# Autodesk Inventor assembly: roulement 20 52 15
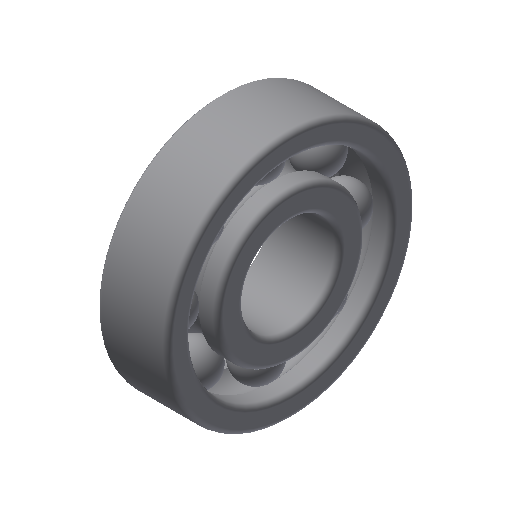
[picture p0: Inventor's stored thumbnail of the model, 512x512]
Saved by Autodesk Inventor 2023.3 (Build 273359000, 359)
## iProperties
Created: 2012-12
Part Number: roulement 20 52 15
Document SubType Name: Assembly
Designer: jost thierry
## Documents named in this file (4)
- E:\Dossier technique\Reducteur\TD02-Reducteur S37\TD02-Reducteur-Ressources\TD02-Reduct-3D\roulement 20 52 15.iam
- E:\Dossier technique\Reducteur\TD02-Reducteur S37\TD02-Reducteur-Ressources\TD02-Reduct-3D\BI 20 52.ipt
- E:\Dossier technique\Reducteur\TD02-Reducteur S37\TD02-Reducteur-Ressources\TD02-Reduct-3D\BILLE 20 52.ipt
- E:\Dossier technique\Reducteur\TD02-Reducteur S37\TD02-Reducteur-Ressources\TD02-Reduct-3D\BE 20 52.ipt
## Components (10 placed, 3 different names)
1. BI 20 52:1
2. BILLE 20 52:1
3. BE 20 52:1
4. BILLE 20 52:2
5. BILLE 20 52:3
6. BILLE 20 52:4
7. BILLE 20 52:5
8. BILLE 20 52:6
9. BILLE 20 52:7
10. BILLE 20 52:8
